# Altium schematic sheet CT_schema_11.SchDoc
size 387 x 385 mm
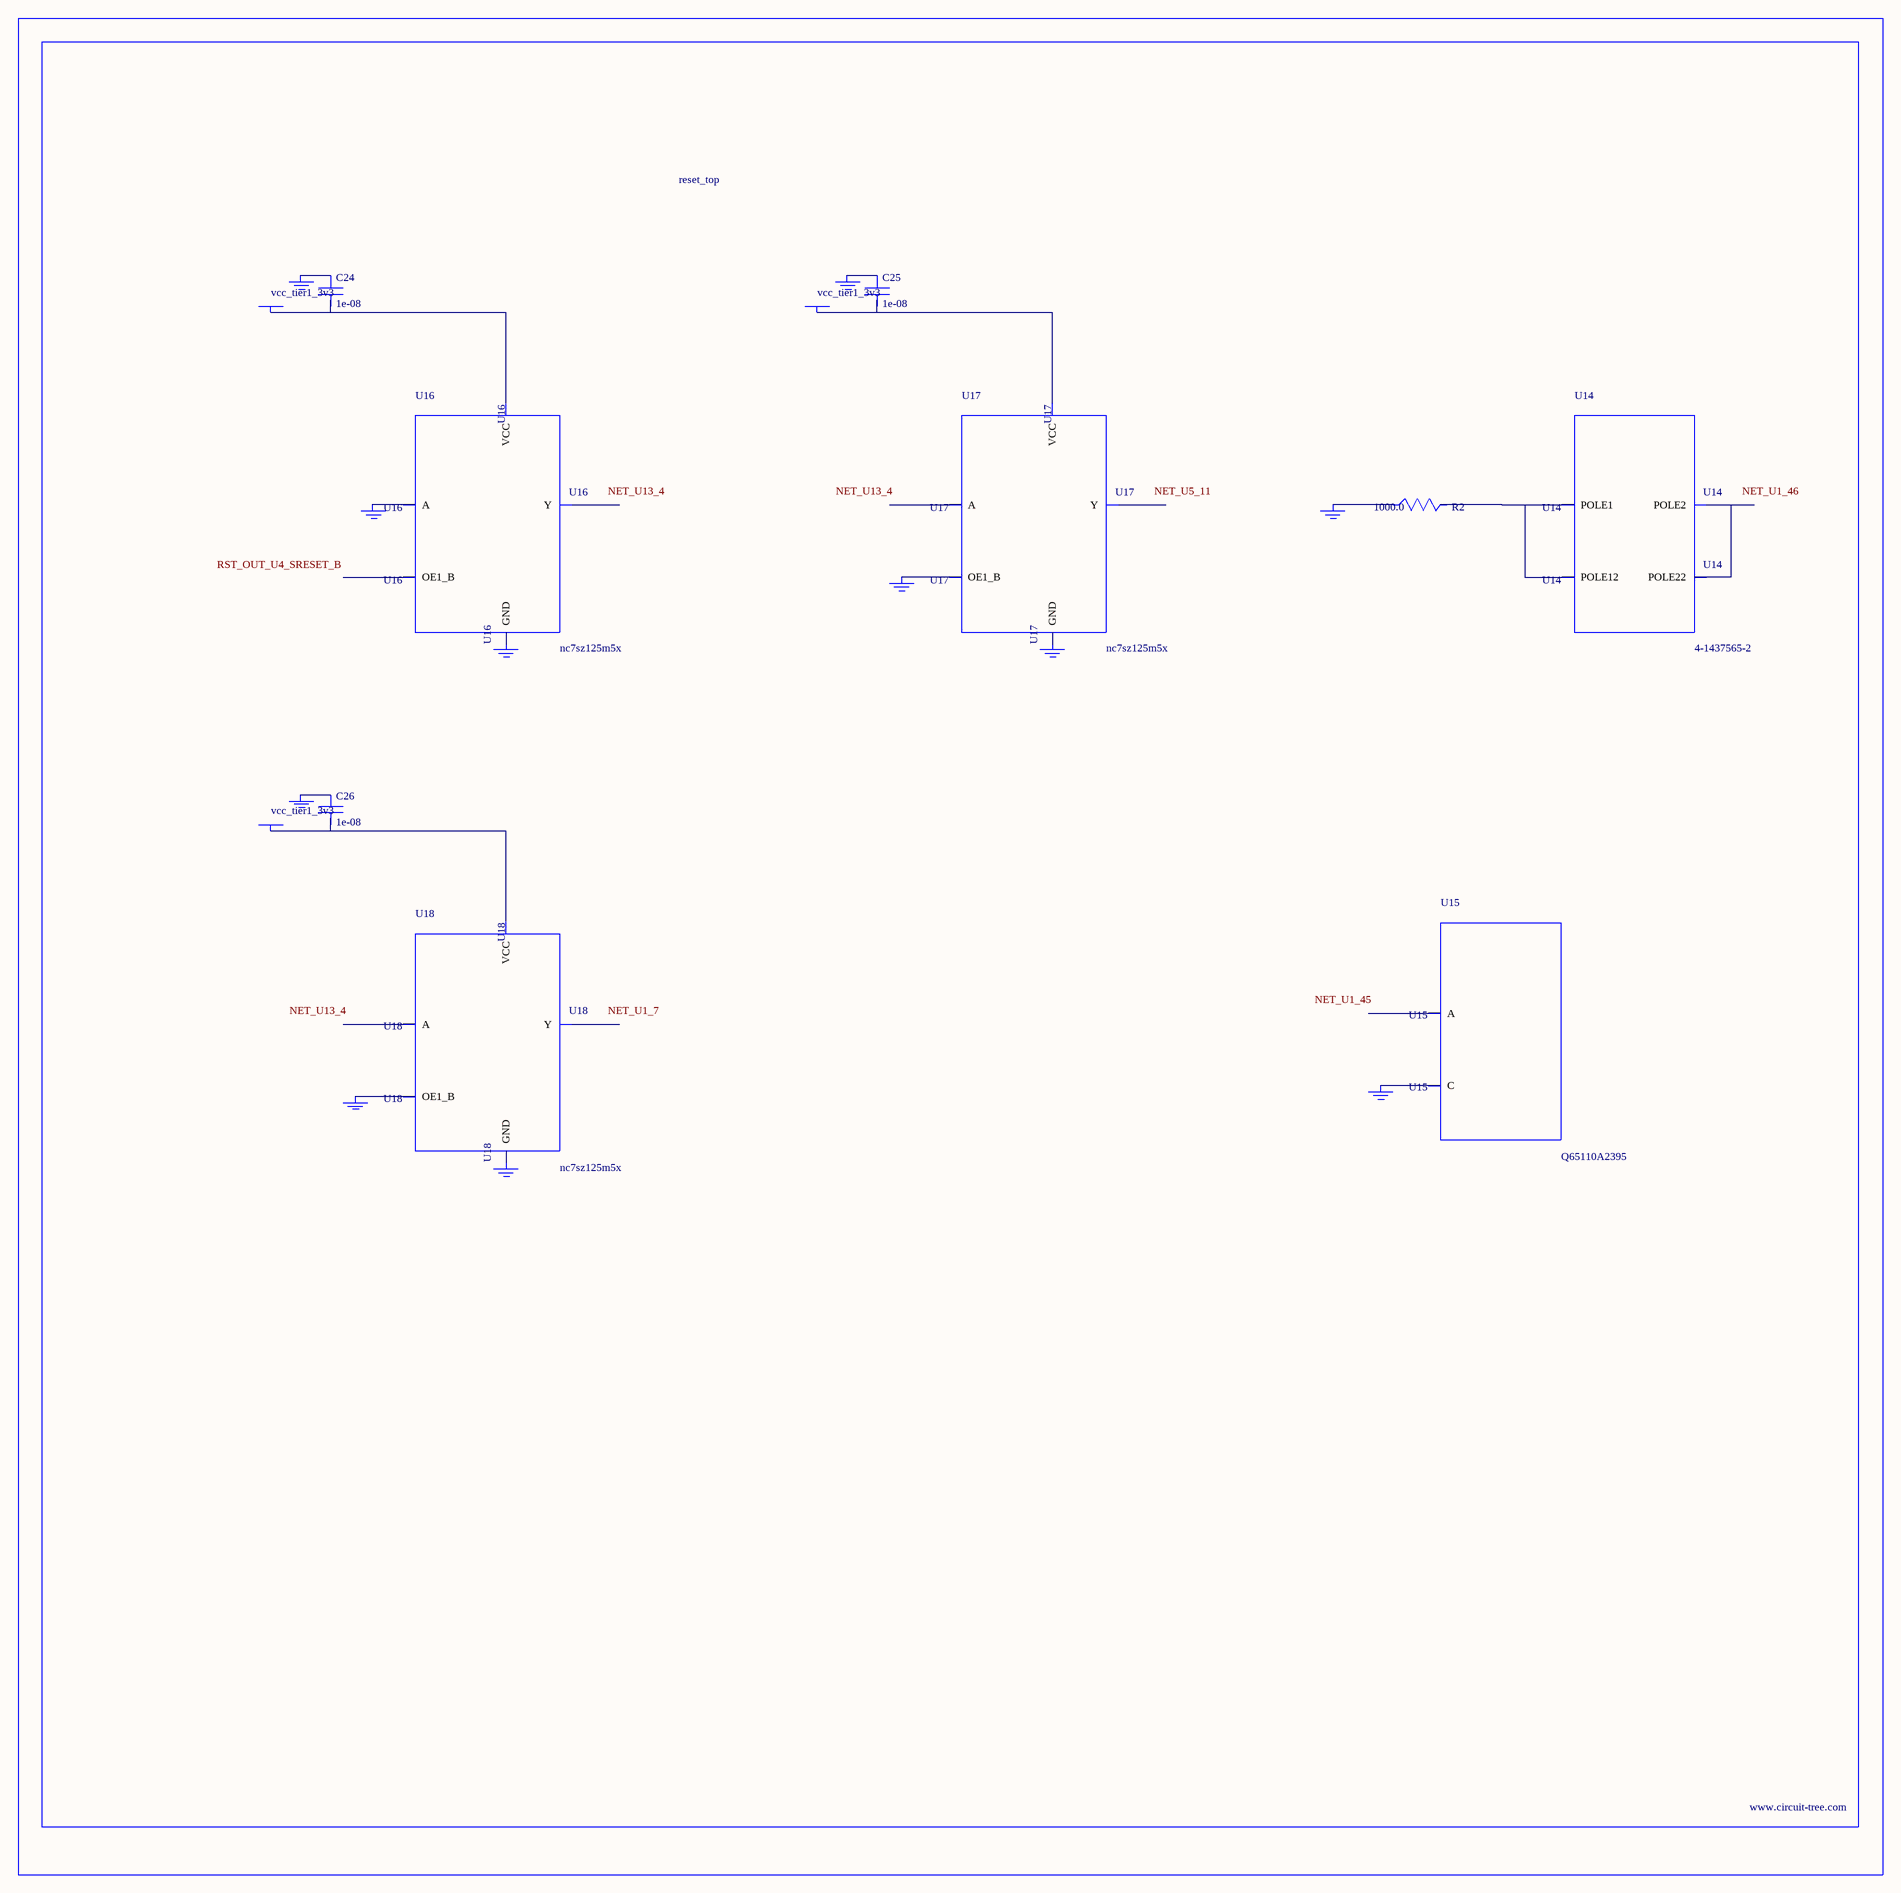
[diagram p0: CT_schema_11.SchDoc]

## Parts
BORDER10  (no value)
C24  1e-08  [C0402]
C25  1e-08  [C0402]
C26  1e-08  [C0402]
GND_INSTANCE_10_0  (no value)
GND_INSTANCE_10_1  (no value)
GND_INSTANCE_10_2  (no value)
GND_INSTANCE_10_3  (no value)
GND_INSTANCE_10_4  (no value)
GND_INSTANCE_10_5  (no value)
GND_INSTANCE_10_6  (no value)
GND_INSTANCE_10_7  (no value)
GND_INSTANCE_10_8  (no value)
GND_INSTANCE_10_9  (no value)
GND_INSTANCE_10_10  (no value)
POWER_INSTANCE_10_0  vcc_tier1_3v3
POWER_INSTANCE_10_1  vcc_tier1_3v3
POWER_INSTANCE_10_2  vcc_tier1_3v3
R2  1000.0  [R0603]
U14  4-1437565-2  [SW_4-1437565-2]
U15  Q65110A2395  [LGM67K-G1J2-24-Z]
U16  nc7sz125m5x  [NC7SZ125M5X]
U17  nc7sz125m5x  [NC7SZ125M5X]
U18  nc7sz125m5x  [NC7SZ125M5X]

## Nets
NetC24_1: C24.1 GND_INSTANCE_10_2.0(GND)
NetC24_2: C24.2 POWER_INSTANCE_10_0.0(PWR) U16.5(VCC)
NetC25_1: C25.1 GND_INSTANCE_10_5.0(GND)
NetC25_2: C25.2 POWER_INSTANCE_10_1.0(PWR) U17.5(VCC)
NetC26_1: C26.1 GND_INSTANCE_10_8.0(GND)
NetC26_2: C26.2 POWER_INSTANCE_10_2.0(PWR) U18.5(VCC)
NetGND_INSTANCE_10_0_0: GND_INSTANCE_10_0.0(GND) R2.1
NetGND_INSTANCE_10_1_0: GND_INSTANCE_10_1.0(GND) U15.C
NetGND_INSTANCE_10_3_0: GND_INSTANCE_10_3.0(GND) U16.2(A)
NetGND_INSTANCE_10_4_0: GND_INSTANCE_10_4.0(GND) U16.3(GND)
NetGND_INSTANCE_10_6_0: GND_INSTANCE_10_6.0(GND) U17.1(OE1_B)
NetGND_INSTANCE_10_7_0: GND_INSTANCE_10_7.0(GND) U17.3(GND)
NetGND_INSTANCE_10_9_0: GND_INSTANCE_10_9.0(GND) U18.1(OE1_B)
NetGND_INSTANCE_10_10_0: GND_INSTANCE_10_10.0(GND) U18.3(GND)
NetR2_2: R2.2 U14.1(POLE1) U14.2(POLE12)
NetU14_3: U14.3(POLE2) U14.4(POLE22)

Not connected (* = marked no-connect by the designer): U15 A; U16 1(OE1_B) 4(Y); U17 2(A) 4(Y); U18 2(A) 4(Y)

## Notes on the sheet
- Labels drawn without touching a wire or pin: NET_U1_7, NET_U1_45, NET_U1_46, NET_U5_11, NET_U13_4, RST_OUT_U4_SRESET_B

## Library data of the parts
BORDER10 = BORDER_PAGE10
C24-C26 = C0402C103K3RAC
GND_INSTANCE_10_0-GND_INSTANCE_10_10 = GND
POWER_INSTANCE_10_0-POWER_INSTANCE_10_2 = PWR
R2 = RC0603JR-071KL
